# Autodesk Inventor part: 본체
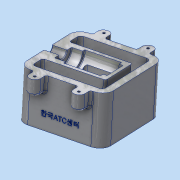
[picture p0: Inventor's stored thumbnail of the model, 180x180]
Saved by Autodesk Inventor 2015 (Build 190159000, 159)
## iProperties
Created: 2018-01
Part Number: 본체
Material: 알루미늄 6061
Document SubType Name: Modeling
Designer: SCD-A011
Density: 2.7 g/cm^3
Appearance: 알루미늄 - 평지
Mass: 995.107 g
Surface Area: 834.704 cm^2
Volume: 368.558 cm^3
Author: SCD-A011
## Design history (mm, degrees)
sketch "스케치3"
  geometry: L1 (0, 0)-(110, 0); L2 (110, 0)-(110, 65); L3 (110, 65)-(0, 65); L4 (0, 65)-(0, 0); L5 (0, 65)-(19, 65); L6 (19, 65)-(19, 57.5); L7 (19, 57.5)-(0, 57.5); L8 (0, 57.5)-(0, 65); L9 (19, 65)-(33, 65); L10 (33, 65)-(33, 49); L11 (33, 49)-(19, 49); L12 (19, 49)-(19, 65); L13 (33, 65)-(80, 65); L14 (80, 65)-(80, 45); L15 (80, 45)-(33, 45); L16 (33, 45)-(33, 65); L17 (80, 65)-(85, 65); L18 (85, 65)-(85, 50); L19 (85, 50)-(80, 50); L20 (80, 50)-(80, 65); L21 (0, 65)-(110, 65); L22 (110, 65)-(110, 0); L23 (110, 0)-(0, 0); L24 (0, 0)-(0, 65)
  constraints: 48 end point, 12 parallel, 6 horizontal, 6 perpendicular
  dimensions: "d4" = 110 distance of L2.end L3.end; "d5" = 65 distance of L1.end L2.end; "d6" = 19 distance of L6.end L7.end; "d7" = 7.5 distance of L5.end L6.end; "d8" = 14 distance of L10.end L11.end; "d9" = 16 distance of L9.end L10.end; "d10" = 47 distance of L14.end L15.end; "d11" = 20 distance of L13.end L14.end; "d12" = 5 distance of L18.end L19.end; "d13" = 15 distance of L17.end L18.end
extrude "돌출1" new body sketch "스케치3" stored distance "d14" = 110; taper "d15" = 0 deg
revolve "회전1" stored, may be unused: angle "d16" = 90 deg
sketch "스케치4"
  geometry: L1 (0, 0)-(0, -45); L2 (0, 0)-(45, 0); L3 (0, -45)-(-100, -45); L4 (-100, -45)-(-100, 45); L5 (-100, 45)-(-10, 45); L6 (-10, 45)-(-10, 25); L7 (-10, 25)-(-90, 25); L8 (-90, 25)-(-90, -25); L9 (-90, -25)-(0, -25); L10 (0, -25)-(-10, -25); L11 (-10, -25)-(-10, -45)
  constraints: 22 end point, 7 perpendicular, 2 point on line, 1 horizontal, 1 parallel
  dimensions: "d18" = 90 deg angle of L1 L2 (derived); "d19" = 100 distance of L1.end L3.end; "d20" = 90 distance of L3.end L4.end; "d21" = 90 deg angle of L3 L4 (derived); "d22" = 90 distance of L4.end L5.end; "d23" = 90 deg angle of L4 L5 (derived); "d24" = 20 distance of L5.end L6.end; "d25" = 90 deg angle of L5 L6 (derived); "d26" = 80 distance of L6.end L7.end; "d27" = 90 deg angle of L6 L7 (derived); "d28" = 50 distance of L7.end L8.end; "d29" = 90 deg angle of L8 L7 (derived); "d30" = 90 distance of L8.end L9.end; "d31" = 90 deg angle of L9 L8 (derived); "d32" = 10 distance of L9.end L10.end
extrude "돌출2" cut sketch "스케치4" distance "d33" = 65; taper "d34" = 0 deg
sketch "스케치5"
  geometry: L1 (90, 0)-(90, 65) reference; L2 (90, 65)-(90, 30); L3 (90, 65)-(125, 65); L4 (90, 30)-(10, 8.564); L5 (10, 0)-(10, 65) reference; L6 (100, 0)-(100, 65) reference; L7 (100, 65)-(90, 65); L8 (10, 65)-(100, 65) reference; L9 (100, 0)-(10, 0); L10 (100, 0)-(100, 65) reference; 1 further point
  constraints: 10 end point, 2 collinear, 2 perpendicular, 1 horizontal, 1 point on line
  dimensions: "d35" = 35 distance of L1.end L2.end; "d36" = 90 deg angle of L2 L3 (derived); "d38" = 105 deg angle of L2 L4
extrude "돌출3" cut sketch "스케치5" stored distance "d39" = 50; taper "d40" = 0 deg
sketch "스케치7"
  geometry: L1 (10, 65)-(100, 65) reference; L2 (0, 65)-(55, 65); L3 (80, 45)-(33, 45) reference; L4 (56.5, 45)-(75, 45); L5 (10, 8.564)-(90, 30) reference; L6 (0, 11.061)-(75, 31.157); L7 (75, 45)-(75, 31.157); L8 (56.5, 45)-(38, 45); L9 (56.5, 45)-(75, 45); L10 (38, 45)-(38, 39.243); L11 (0, 11.061)-(0, 29.061); L12 (0, 65)-(0, 0) reference; L13 (0, 29.061)-(38, 39.243); L14 (38, 45)-(75, 45); L15 (75, 45)-(75, 55); L16 (75, 55)-(38, 55); L17 (38, 55)-(38, 45); L18 (33, 65)-(33, 45) reference; L19 (80, 65)-(80, 45) reference; L20 (0, 0)-(110, 0) reference
  constraints: 26 end point, 3 horizontal, 2 collinear, 2 parallel, 2 perpendicular, 2 point on line, 1 vertical
  dimensions: "d61" = 18.5 distance of L4.start L4.end; "d62" = 5 distance between parallel lines of L6 L5; "d63" = 18.5 distance of L4.start L8.end; "d64" = 180 deg angle of L8 L9 (derived); "d65" = 18 distance of L6.start L11.end; "d66" = 105 deg angle of L11 L13; "d67" = 37 distance of L16.end L15.end; "d108" = 5 distance between parallel lines of L17 L18; "d109" = 5 distance between parallel lines of L19 L15 (derived); "d110" = 31.15714 distance from line of L20 L6.end
extrude "돌출4" cut sketch "스케치7" stored distance "d69" = 30; taper "d70" = 0 deg
sketch "스케치8"
  geometry: L1 (110, 0)-(0, 0) reference; L2 (110, 110)-(110, 0) reference; L3 (34.5, 120)-(34.5, 110); L4 (19.5, 120)-(19.5, 110); L5 (19.5, 110)-(34.5, 110); L6 (0, 55)-(110, 55); L7 (0, 110)-(110, 110) reference; L8 (55, 110)-(55, 0); L9 (90.5, 110)-(75.5, 110); L10 (75.5, 120)-(75.5, 110); L11 (90.5, 120)-(90.5, 110); L12 (19.5, 0)-(34.5, 0); L13 (19.5, -10)-(19.5, 0); L14 (34.5, -10)-(34.5, 0); L15 (75.5, -10)-(75.5, 0); L16 (90.5, 0)-(75.5, 0); L17 (90.5, -10)-(90.5, 0); A1 r 7.5 centre (27, 120) between (34.5, 120) and (19.5, 120); A2 r 7.5 centre (83, 120) between (90.5, 120) and (75.5, 120); A3 r 7.5 centre (27, -10) between (19.5, -10) and (34.5, -10); A4 r 7.5 centre (83, -10) between (75.5, -10) and (90.5, -10)
  constraints: 28 end point, 15 symmetric about line, 8 point on circle, 4 centre point, 3 midpoint, 2 tangent, 1 horizontal, 3 other
extrude "돌출5" join sketch "스케치8" distance "d75" = 20; taper "d76" = 0 deg
fillet "모깎기1" dims "d77" = 1
fillet "모깎기2" dims "d78" = 5
fillet "모깎기3" dims "d79" = 3
fillet "모깎기4" dims "d80" = 15
fillet "모깎기6" dims "d82" = 3
fillet "모깎기7" dims "d83" = 3
chamfer "모따기1" distance "d84" = 1; stored, may be unused: second distance "d85" = 2, angle "d86" = 45 deg
sketch "스케치9"
  geometry: A1 r 7.5 centre (0, 0) between (-7.5, 0) and (7.5, 0) reference; A2 r 7.5 centre (56, 0) between (48.5, 0) and (63.5, 0) reference; A3 r 7.5 centre (56, 130) between (63.5, 130) and (48.5, 130) reference; A4 r 7.5 centre (0, 130) between (7.5, 130) and (-7.5, 130) reference; 5 further points
  constraints: 4 coincident
hole "구멍1" sketch "스케치9" at (0, 130), (56, 130), (56, 0), (0, 0) diameter "d87" = 3.459; stored, may be unused: countersink angle "d91" = 90 deg, drill point angle "d93" = 118 deg; dims "d88" = 9, "d89" = 4, "d90" = 2, "d92" = 11
sketch "스케치10"
  geometry: 2 further points
  constraints: 1 other
  dimensions: "d95" = 55 horizontal distance of point (55, 20) point (0, 0); "d96" = 20 vertical distance of point (0, 0) point (55, 20)
feature "엠보싱1" sketch "스케치10" dims "d4" = 110, "d5" = 65, "d6" = 19, "d7" = 7.5, "d8" = 14, "d9" = 16, "d10" = 47, "d11" = 20, "d12" = 5, "d13" = 15, "d97" = 0.5, "d98" = 0
chamfer "모따기2" distance "d99" = 1; stored, may be unused: second distance "d100" = 2, angle "d101" = 45 deg
fillet "모깎기10" dims "d103" = 3
fillet "모깎기11" dims "d104" = 3
fillet "모깎기12" dims "d105" = 3
fillet "모깎기13" dims "d106" = 3
fillet "모깎기14" dims "d107" = 3
node "솔리드1"
